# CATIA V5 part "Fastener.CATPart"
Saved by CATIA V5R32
Part number: Fastener
Bounding box of the stored display mesh (mm): x -4.826 to 4.826, y -4.826 to 4.826, z -47.752 to 0
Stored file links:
  D:\PROJECTS\Project 2022\CATIA V5 6R 2022\Resources\Input file\c14_catia_v5_6r2022_inp\c14_catia_v5_6r2022_inp\Fastener.CATPart
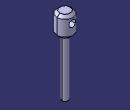
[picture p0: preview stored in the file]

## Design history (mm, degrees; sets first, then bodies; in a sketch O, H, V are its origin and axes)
Body1 (main body)
  Sketch1 on xy-plane, origin (0, 0, 0), H (1, 0, 0), V (0, 1, 0)
    circle A1 centre (0, 0) radius 4.826
    circle A2 centre (0, 0) radius 1.905
    radius A2 = 1.905
    radius A1 = 4.826
  MultiPad1: profile Sketch1, domains (length 0 / length 47.752; length 0 / length 12.7)
  Chamfer1: length 1.5875, angle 45, on 2 edges
  Chamfer2: length 0.508, angle 45, on 1 edge
  Sketch2 on zx-plane, origin (-1.612, 0, 1.612), H (1, 0, 0), V (0, 0, -1)
    point P1 (1.612, 6.35)
    reference intersected line E1 through (1.612, 0) direction (0, 1) from yz-plane
    distance P1 H = 6.35
    coincidence: E1 P1
  Hole1: placed by Sketch2, at (0, 0, -4.738) direction (0, -1, 0), diameter 4.064, depth 10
